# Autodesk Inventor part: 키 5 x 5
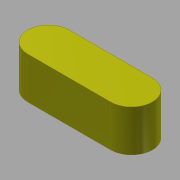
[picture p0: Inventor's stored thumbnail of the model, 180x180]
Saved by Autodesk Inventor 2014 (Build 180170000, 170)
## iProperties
Created: 2011-04
Part Number: 키 5 x 5
Document SubType Name: Modeling
Designer: pww
Density: 7.86 g/cm^3
Material: 강철, 연강
Appearance: 노란색
Author: pww
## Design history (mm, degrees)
sketch "스케치1"
  geometry: L1 (-5, -2.5)-(5, -2.5); L2 (5, 2.5)-(-5, 2.5); A1 r 2.5 centre (-5, 0) between (-5, 2.5) and (-5, -2.5); A2 r 2.5 centre (5, 0) between (5, -2.5) and (5, 2.5); 1 further point
  constraints: 4 end point, 4 point on circle, 2 centre point
extrude "돌출1" new body sketch "스케치1" distance "d0" = 5; taper "d1" = 0 deg
node "솔리드1"
